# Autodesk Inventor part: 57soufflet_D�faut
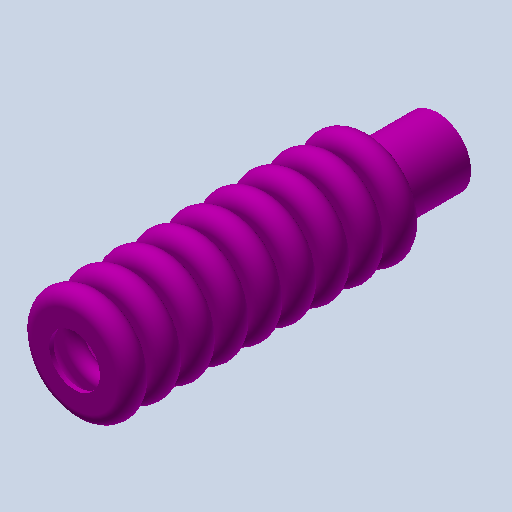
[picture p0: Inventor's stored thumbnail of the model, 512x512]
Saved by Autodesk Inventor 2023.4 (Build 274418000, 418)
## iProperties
Created: 2011-01
Part Number: 57soufflet_D�faut
Document SubType Name: Modeling
Designer: eric
Density: 1 g/cm^3
Mass: 1.51924 g
Surface Area: 48.345 cm^2
Volume: 1.51924 cm^3
Material: Générique
Appearance: Magenta
Author: eric
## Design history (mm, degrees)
feature "Base1"
node "Corps solides"
node "Corps surfaciques"
node "Solide1"
